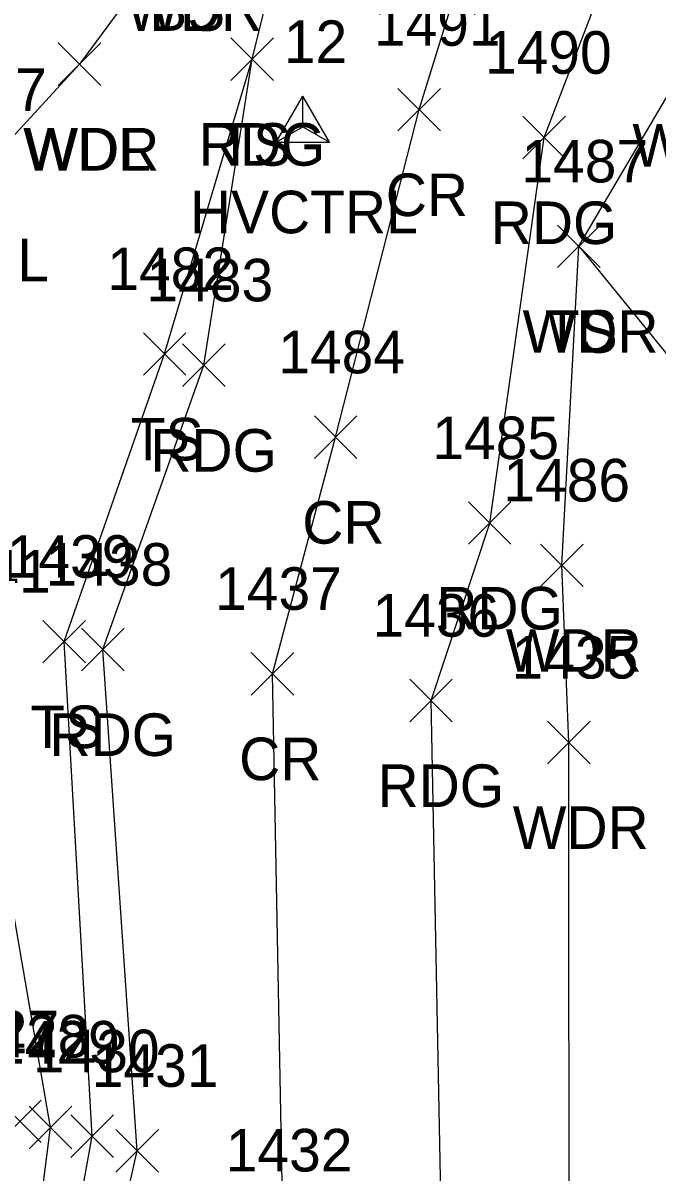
# Model space of a CAD drawing. Extents: x 1600281 to 1602254, y 862855 to 863227.
# Drawn here: x 1602017.5 to 1602047.3, y 862978.2 to 863032.2 of the extents above; entities that cross this region are included whole.
import ezdxf

# ---------------------------------------------------------------- set-up
doc = ezdxf.new("R2010")
doc.units = 0
for name, color, linetype in [('C_A', 7, 'Continuous'), ('C_I', 7, 'Continuous'), ('CPSM', 7, 'Continuous'), ('L_A', 7, 'Continuous'), ('L_I', 7, 'Continuous'), ('L_TIC', 7, 'Continuous'), ('LAWA', 7, 'Continuous'), ('LELB', 7, 'Continuous'), ('P_A', 7, 'Continuous'), ('P_I', 7, 'Continuous'), ('P_TIC', 7, 'Continuous'), ('PEU', 7, 'Continuous'), ('PRC', 7, 'Continuous')]:
    doc.layers.add(name, color=color, linetype=linetype)

msp = doc.modelspace()

# ---------------------------------------------------------------- linework, layer by layer
at = {"layer": 'CPSM'}
for p, q in [((1602029.365, 863026.591), (1602030.615, 863028.756)), ((1602031.865, 863026.591), (1602030.615, 863028.756)), ((1602030.615, 863027.312), (1602030.615, 863028.756)), ((1602029.365, 863026.591), (1602030.615, 863027.312)), ((1602030.615, 863027.312), (1602030.615, 863027.312)), ((1602030.615, 863027.312), (1602031.865, 863026.591)), ((1602029.365, 863026.591), (1602031.865, 863026.591))]:
    msp.add_line(p, q, dxfattribs=at)
at = {"layer": 'L_TIC'}
for points in [[(1602027.234, 863029.488), (1602029.234, 863031.488)], [(1602029.234, 863029.488), (1602027.234, 863031.488)], [(1602019.118, 863029.26), (1602021.118, 863031.26)], [(1602021.118, 863029.26), (1602019.118, 863031.26)], [(1602019.118, 863029.26), (1602021.118, 863031.26)], [(1602021.118, 863029.26), (1602019.118, 863031.26)], [(1602042.565, 863020.702), (1602044.565, 863022.702)], [(1602044.565, 863020.702), (1602042.565, 863022.702)], [(1602042.565, 863020.702), (1602044.565, 863022.702)], [(1602044.565, 863020.702), (1602042.565, 863022.702)], [(1602023.121, 863015.644), (1602025.121, 863017.644)], [(1602025.121, 863015.644), (1602023.121, 863017.644)], [(1602041.776, 863005.718), (1602043.776, 863007.718)], [(1602043.776, 863005.718), (1602041.776, 863007.718)], [(1602018.404, 863002.133), (1602020.404, 863004.133)], [(1602020.404, 863002.133), (1602018.404, 863004.133)], [(1602042.104, 862997.4), (1602044.104, 862999.4)], [(1602044.104, 862997.4), (1602042.104, 862999.4)], [(1602016.327, 862979.602), (1602018.327, 862981.602)], [(1602018.327, 862979.602), (1602016.327, 862981.602)], [(1602017.761, 862979.317), (1602019.761, 862981.317)], [(1602019.761, 862979.317), (1602017.761, 862981.317)], [(1602019.715, 862978.907), (1602021.715, 862980.907)], [(1602021.715, 862978.907), (1602019.715, 862980.907)]]:
    msp.add_lwpolyline(points, dxfattribs=at)
at = {"layer": 'LAWA'}
for points in [[(1601898.678, 863064.416), (1601911.709, 863050.949), (1601935.902, 863043.881), (1601947.495, 863033.023), (1601951.399, 863041.53), (1601951.325, 863053.197), (1601949.991, 863060.087), (1601958.573, 863066.845), (1601964.294, 863071.516), (1601970.831, 863066.786), (1601979.179, 863061.535), (1601987.871, 863058.21), (1601991.577, 863057.216), (1602006.602, 863051.128), (1602014.671, 863047.985), (1602025.678, 863046.601), (1602024.954, 863036.82), (1602020.118, 863030.26)], [(1602013.88, 862864.604), (1602012.852, 862879.286), (1602012.389, 862885.249), (1602013.668, 862890.426), (1602013.993, 862891.89), (1602014.423, 862895.34), (1602031.133, 862915.343), (1602041.823, 862936.999), (1602041.484, 862949.365), (1602043.119, 862970.368), (1602043.104, 862998.4), (1602042.776, 863006.718), (1602043.565, 863021.702), (1602048.724, 863030.448), (1602052.915, 863023.582), (1602057.074, 863015.497), (1602062.849, 863014.974)], [(1601918.484, 862969.325), (1601939.42, 862962.53), (1601955.985, 862947.407), (1601971.758, 862937.876), (1601975.725, 862943.556), (1601990.974, 862965.699), (1602006.102, 862971.122), (1602011.441, 862985.305), (1602010.41, 863001.058), (1602007, 863006.956), (1602005.728, 863016.362), (1602007.852, 863017.624), (1602015.328, 863025.061), (1602020.118, 863030.26)]]:
    msp.add_lwpolyline(points, dxfattribs=at)
at = {"layer": 'LELB'}
for points in [[(1601850.487, 862982.969), (1601860.819, 862978.517), (1601879.357, 862968.779), (1601889.404, 862966.06), (1601913.787, 862945.707), (1601936.178, 862934.785), (1601958.999, 862928.536), (1601973.106, 862927.744), (1601983.044, 862929.485), (1601994.912, 862935.464), (1602008.175, 862945.227), (1602016.316, 862961.337), (1602018.761, 862980.317), (1602014.943, 863002.438), (1602007.852, 863017.624), (1602006.36, 863023.315), (1602003.161, 863037.99), (1602002.758, 863044.77), (1602006.602, 863051.128), (1602010.649, 863053.195)], [(1601985.88, 862928.206), (1601996.377, 862933.331), (1602008.175, 862945.227), (1602011.909, 862944.998), (1602017.285, 862960.892), (1602020.715, 862979.907), (1602019.404, 863003.133), (1602024.121, 863016.644), (1602028.234, 863030.488)], [(1602043.565, 863021.702), (1602050.721, 863012.929), (1602058.497, 862993.658), (1602059.334, 862987.347), (1602055.31, 862972.472), (1602061.28, 862961.826)]]:
    msp.add_lwpolyline(points, dxfattribs=at)
at = {"layer": 'P_TIC'}
for points in [[(1602027.234, 863029.488), (1602029.234, 863031.488)], [(1602029.234, 863029.488), (1602027.234, 863031.488)], [(1602035.072, 863027.12), (1602037.072, 863029.12)], [(1602037.072, 863027.12), (1602035.072, 863029.12)], [(1602040.945, 863025.807), (1602042.945, 863027.807)], [(1602042.945, 863025.807), (1602040.945, 863027.807)], [(1602024.961, 863015.116), (1602026.961, 863017.116)], [(1602026.961, 863015.116), (1602024.961, 863017.116)], [(1602031.15, 863011.734), (1602033.15, 863013.734)], [(1602033.15, 863011.734), (1602031.15, 863013.734)], [(1602038.384, 863007.705), (1602040.384, 863009.705)], [(1602040.384, 863007.705), (1602038.384, 863009.705)], [(1602020.224, 863001.762), (1602022.224, 863003.762)], [(1602022.224, 863001.762), (1602020.224, 863003.762)], [(1602028.185, 863000.626), (1602030.185, 863002.626)], [(1602030.185, 863000.626), (1602028.185, 863002.626)], [(1602035.63, 862999.366), (1602037.63, 863001.366)], [(1602037.63, 862999.366), (1602035.63, 863001.366)], [(1602021.827, 862978.222), (1602023.827, 862980.222)], [(1602023.827, 862978.222), (1602021.827, 862980.222)]]:
    msp.add_lwpolyline(points, dxfattribs=at)
at = {"layer": 'PEU'}
for points in [[(1601721.431, 862942.479), (1601759.391, 862940.415), (1601795.476, 862935.046), (1601824.436, 862931.284), (1601871.597, 862925.252), (1601900.947, 862923.392), (1601930.539, 862915.155), (1601956.45, 862910.483), (1601973.532, 862907.721), (1601992.866, 862904.836), (1602011.433, 862910.06), (1602025.54, 862921.56), (1602034.602, 862951.409), (1602037.167, 862973.137), (1602036.63, 863000.366), (1602039.384, 863008.705), (1602041.945, 863026.807), (1602046.402, 863038.482), (1602048.205, 863041.762), (1602041.548, 863045.817), (1602034.191, 863049.728), (1602032.199, 863046.614)], [(1601722.644, 862959.622), (1601760.787, 862956.047), (1601799.291, 862951.588), (1601828.839, 862949.757), (1601875.052, 862946.506), (1601907.829, 862943.545), (1601935.488, 862931.229), (1601958.787, 862926.456), (1601973.443, 862925.266), (1601984.384, 862925.961), (1601999.67, 862930.135), (1602015.041, 862942.762), (1602018.564, 862960.181), (1602022.827, 862979.222), (1602021.224, 863002.762), (1602025.961, 863016.116), (1602028.234, 863030.488), (1602032.199, 863046.614)]]:
    msp.add_lwpolyline(points, dxfattribs=at)
at = {"layer": 'PRC'}
msp.add_lwpolyline([(1601722.025, 862950.916), (1601760.349, 862947.65), (1601797.645, 862942.059), (1601826.101, 862939.873), (1601874.376, 862936.203), (1601906.559, 862932.665), (1601933.522, 862923.273), (1601957.927, 862920.037), (1601974.083, 862916.229), (1601989.499, 862915.675), (1602005.127, 862920.564), (1602020.051, 862931.206), (1602025.884, 862956.798), (1602029.684, 862975.246), (1602029.185, 863001.626), (1602032.15, 863012.734), (1602036.072, 863028.12), (1602041.548, 863045.817)], dxfattribs=at)

# ---------------------------------------------------------------- texts
at = {"layer": 'C_A'}
msp.add_text('HVCTRL', height=2, dxfattribs=at).set_placement((1602025.308, 863022.312))
at = {"layer": 'C_I'}
msp.add_text('12', height=2, dxfattribs=at).set_placement((1602029.718, 863030.312))
at = {"layer": 'L_A'}
for s, p in [('WDR', (1602022.316, 863031.82)), ('BS', (1602023.395, 863031.82)), ('WDR', (1602017.48, 863025.26)), ('WDL', (1602017.535, 863025.26)), ('TS', (1602026.643, 863025.488)), ('WDR', (1602046.086, 863025.448)), ('WDL', (1602012.745, 863020.061)), ('WDR', (1602040.927, 863016.702)), ('TS', (1602041.974, 863016.702)), ('TS', (1602022.531, 863011.644)), ('WDR', (1602040.138, 863001.718)), ('TS', (1602017.814, 862998.133)), ('WDR', (1602040.466, 862993.4))]:
    msp.add_text(s, height=2, dxfattribs=at).set_placement(p)
at = {"layer": 'L_I'}
for s, p in [('1447', (1602012.635, 863028.061)), ('1487', (1602040.872, 863024.702)), ('1487', (1602040.872, 863024.702)), ('1482', (1602021.428, 863019.644)), ('1486', (1602040.028, 863009.718)), ('1439', (1602016.704, 863006.133)), ('1441', (1602012.817, 863005.438)), ('1435', (1602040.411, 863001.4)), ('1427', (1602013.213, 862983.796)), ('1428', (1602014.634, 862983.602)), ('1429', (1602016.06, 862983.317)), ('1430', (1602017.935, 862982.907))]:
    msp.add_text(s, height=2, dxfattribs=at).set_placement(p)
at = {"layer": 'P_A'}
for s, p in [('RDG', (1602025.722, 863025.488)), ('CR', (1602034.505, 863023.12)), ('RDG', (1602039.433, 863021.807)), ('RDG', (1602023.449, 863011.116)), ('CR', (1602030.583, 863007.734)), ('RDG', (1602036.873, 863003.705)), ('RDG', (1602018.712, 862997.762)), ('CR', (1602027.618, 862996.626)), ('RDG', (1602034.118, 862995.366))]:
    msp.add_text(s, height=2, dxfattribs=at).set_placement(p)
at = {"layer": 'P_I'}
for s, p in [('1491', (1602033.946, 863031.12)), ('1490', (1602039.165, 863029.807)), ('1483', (1602023.268, 863019.116)), ('1484', (1602029.457, 863015.734)), ('1485', (1602036.691, 863011.705)), ('1438', (1602018.531, 863005.762)), ('1437', (1602026.492, 863004.626)), ('1436', (1602033.882, 863003.366)), ('1431', (1602020.701, 862982.222)), ('1432', (1602026.991, 862978.246))]:
    msp.add_text(s, height=2, dxfattribs=at).set_placement(p)

doc.saveas('drawing.dxf')
